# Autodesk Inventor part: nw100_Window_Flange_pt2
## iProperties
Shininess: 64.0
Length Units: 11269
Angle Units: 11279
Time Units: 11290
Mass Units: 11283
Length Display Precision: 3
Angle Display Precision: 2
Compacted: True
Part Number: nw100_Window_Flange_pt2
Document SubType Name: Modeling
Created: 2003-05
Designer: John Blackburn
Material: Stainless Steel, 440C
Density: 0.0
Volumn: 0.0
Area: 0.0
PropertySet Name: Model Information
Control State: 0
Master: False
Checked Out: False
Author: John Blackburn
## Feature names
1. Revolution1
2. Chamfer1
3. Hole1
4. Circular Pattern2
